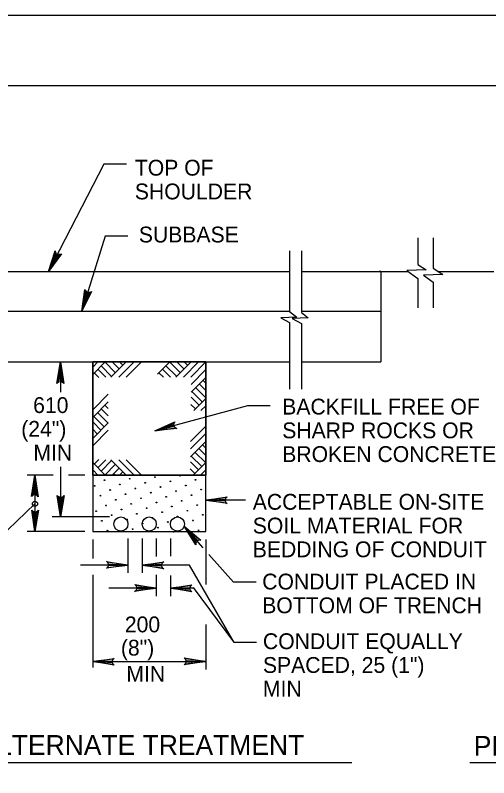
# Model space of a CAD drawing. Extents: x 638448 to 639352, y 297825 to 299013.
# Drawn here: x 638554 to 638654.5, y 298851.5 to 299013.3 of the extents above; entities that cross this region are included whole.
import ezdxf

# ---------------------------------------------------------------- set-up
doc = ezdxf.new("R2010")
doc.units = 0
for name, color, linetype in [('1', 7, 'Continuous'), ('2', 7, 'Continuous'), ('3', 7, 'Continuous'), ('PLT-BNDY', 7, 'Continuous')]:
    doc.layers.add(name, color=color, linetype=linetype)

msp = doc.modelspace()

# ---------------------------------------------------------------- linework, layer by layer
at = {"layer": '1'}
msp.add_lwpolyline([(639272.65, 298434.29), (639272.65, 298998.29), (638486.65, 298998.29), (638486.65, 298434.29), (639272.65, 298434.29), (639272.65, 298460.65), (639072.65, 298460.65), (639072.65, 298525.33), (639272.65, 298525.33), (639272.65, 298554.29), (639072.65, 298554.29), (639072.65, 298434.29), (639151.45, 298434.29), (639151.45, 298460.65), (639151.45, 298434.29), (639228.45, 298434.29), (639228.45, 298460.65), (639228.45, 298448.33), (639272.65, 298448.33)], dxfattribs=at)
at = {"layer": '2'}
for p, q in [((638639.45, 298966.09), (638639.45, 298960.41)), ((638642.76, 298966.09), (638642.76, 298959.6)), ((638612.25, 298963.29), (638612.25, 298950.46)), ((638614.79, 298963.29), (638614.79, 298950.24)), ((638552.44, 298958.93), (638612.25, 298958.93)), ((638614.79, 298958.93), (638637.42, 298958.93)), ((638631.64, 298958.93), (638631.26, 298958.93)), ((638631.64, 298958.93), (638631.64, 298939.73)), ((638643.81, 298958.93), (638655.64, 298958.93)), ((638639.45, 298957.41), (638639.45, 298951.24)), ((638642.76, 298956.63), (638642.76, 298951.24)), ((638552.44, 298950.53), (638612.25, 298950.53)), ((638614.79, 298950.53), (638631.64, 298950.53)), ((638612.25, 298948.07), (638612.25, 298933.98)), ((638614.79, 298947.88), (638614.79, 298933.98)), ((638552.44, 298939.73), (638612.25, 298939.73)), ((638563.63, 298939.73), (638563.63, 298933.31)), ((638570.44, 298937.08), (638573.09, 298939.73)), ((638571.56, 298939.73), (638570.44, 298938.61)), ((638572.24, 298938.88), (638574.47, 298936.65)), ((638573.02, 298939.73), (638575.3, 298937.45)), ((638574.33, 298936.5), (638577.58, 298939.75)), ((638574.58, 298939.73), (638576.06, 298938.24)), ((638575.98, 298936.5), (638579.17, 298939.69)), ((638576.15, 298939.73), (638576.86, 298939.02)), ((638577.53, 298936.5), (638580.73, 298939.69)), ((638584.18, 298937.1), (638586.83, 298939.75)), ((638585.98, 298938.91), (638588.21, 298936.68)), ((638586.76, 298939.75), (638589.04, 298937.47)), ((638588.07, 298936.52), (638591.32, 298939.77)), ((638588.31, 298939.75), (638589.8, 298938.27)), ((638589.71, 298936.52), (638592.91, 298939.72)), ((638589.89, 298939.75), (638590.59, 298939.05)), ((638591.27, 298936.52), (638594.46, 298939.72)), ((638614.79, 298939.73), (638631.64, 298939.73)), ((638631.64, 298939.73), (638631.64, 298939.73)), ((638570.77, 298937.41), (638571.74, 298936.44)), ((638571.55, 298938.19), (638573.25, 298936.5)), ((638584.51, 298937.44), (638585.48, 298936.47)), ((638585.29, 298938.22), (638586.98, 298936.52)), ((638591.32, 298934.97), (638594.44, 298938.09)), ((638591.32, 298933.33), (638594.44, 298936.44)), ((638594.44, 298935.25), (638593.85, 298935.85)), ((638594.44, 298932.13), (638592.27, 298934.29)), ((638594.44, 298933.68), (638593.07, 298935.05)), ((638570.51, 298929.67), (638573.7, 298932.87)), ((638593.02, 298930.54), (638591.32, 298932.24)), ((638593.71, 298931.23), (638591.48, 298933.46)), ((638570.51, 298928.03), (638573.76, 298931.28)), ((638592.24, 298929.77), (638591.27, 298930.73)), ((638591.9, 298929.43), (638594.44, 298931.97)), ((638573.74, 298926.72), (638571.46, 298929)), ((638573.74, 298928.27), (638572.25, 298929.76)), ((638573.74, 298929.85), (638573.03, 298930.55)), ((638594.44, 298930.44), (638593.43, 298929.43)), ((638572.89, 298925.94), (638570.66, 298928.17)), ((638570.44, 298923.49), (638573.74, 298926.79)), ((638572.2, 298925.25), (638570.51, 298926.94)), ((638591.21, 298922.82), (638594.41, 298926.02)), ((638573.74, 298925.26), (638570.44, 298921.96)), ((638571.42, 298924.47), (638570.46, 298925.44)), ((638591.21, 298921.26), (638594.41, 298924.46)), ((638591.21, 298919.62), (638594.46, 298922.87)), ((638594.44, 298919.86), (638592.95, 298921.35)), ((638594.44, 298921.44), (638593.73, 298922.15)), ((638593.59, 298917.53), (638591.36, 298919.76)), ((638594.44, 298918.31), (638592.16, 298920.59)), ((638570.44, 298918.38), (638573.09, 298915.73)), ((638570.77, 298918.04), (638571.74, 298919.01)), ((638571.55, 298917.27), (638573.25, 298918.96)), ((638572.24, 298916.57), (638574.47, 298918.8)), ((638573.02, 298915.73), (638575.3, 298918.01)), ((638574.33, 298918.96), (638577.58, 298915.71)), ((638575.98, 298918.96), (638579.17, 298915.76)), ((638577.53, 298918.96), (638580.73, 298915.76)), ((638592.9, 298916.84), (638591.21, 298918.53)), ((638591.79, 298915.73), (638594.44, 298918.38)), ((638563.63, 298917.49), (638563.63, 298906.84)), ((638571.56, 298915.73), (638570.44, 298916.85)), ((638574.58, 298915.73), (638576.06, 298917.21)), ((638576.15, 298915.73), (638576.86, 298916.44)), ((638592.12, 298916.06), (638591.16, 298917.03)), ((638594.44, 298916.85), (638593.32, 298915.73)), ((638562.08, 298915.73), (638556.51, 298915.73)), ((638558.19, 298915.73), (638558.19, 298903.73)), ((638568.76, 298915.73), (638565.32, 298915.73)), ((638574.01, 298906.84), (638561.86, 298906.84)), ((638568.76, 298903.73), (638556.51, 298903.73)), ((638568.76, 298903.73), (638556.51, 298903.73)), ((638570.44, 298902.05), (638570.44, 298898)), ((638577.94, 298902.27), (638577.94, 298894.95)), ((638580.94, 298902.27), (638580.94, 298894.95)), ((638583.94, 298902.27), (638583.94, 298898.46)), ((638586.94, 298902.27), (638586.94, 298898.53)), ((638594.44, 298902.05), (638594.44, 298892.54)), ((638577.94, 298896.63), (638567.86, 298896.63)), ((638591.02, 298896.63), (638580.94, 298896.63)), ((638570.44, 298894.55), (638570.44, 298874.89)), ((638583.94, 298894.59), (638583.94, 298890.05)), ((638586.94, 298894.44), (638586.94, 298890.05)), ((638583.94, 298891.73), (638573.86, 298891.73)), ((638591.9, 298891.73), (638586.94, 298891.73)), ((638594.44, 298883.99), (638594.44, 298874.47)), ((638570.44, 298876.15), (638594.44, 298876.15))]:
    msp.add_line(p, q, dxfattribs=at)
for points in [[(638577.61, 298981.7), (638572.81, 298981.7), (638561.04, 298958.93)], [(638577.87, 298966.44), (638573.07, 298966.44), (638568.14, 298950.53)], [(638563.53, 298962.55), (638563.17, 298962.55), (638561.04, 298958.93), (638563.53, 298962.55), (638563.8, 298962.66), (638561.04, 298958.93), (638562.78, 298962.75), (638562.57, 298963.03), (638561.04, 298958.93), (638562.5, 298963.33), (638562.57, 298963.03)], [(638639.45, 298960.41), (638641.24, 298959.26), (638637.16, 298959.12), (638639.45, 298957.41)], [(638642.76, 298959.6), (638644.77, 298958.31), (638640.69, 298958.17), (638642.76, 298956.63)], [(638569.95, 298954.53), (638569.6, 298954.47), (638568.14, 298950.53), (638569.95, 298954.53), (638570.2, 298954.69), (638568.14, 298950.53), (638569.18, 298954.59), (638568.93, 298954.83), (638568.14, 298950.53), (638568.8, 298955.12), (638568.93, 298954.83)], [(638612.25, 298950.46), (638613.78, 298949.2), (638610.38, 298949.07), (638612.25, 298948.07)], [(638614.79, 298950.24), (638616.23, 298949.07), (638612.83, 298948.93), (638614.79, 298947.88)], [(638563.05, 298935.37), (638563.36, 298935.53), (638563.63, 298939.73), (638563.05, 298935.37), (638562.86, 298935.15), (638563.63, 298939.73), (638563.8, 298935.53), (638564.12, 298935.38), (638563.63, 298939.73), (638564.32, 298935.14), (638564.12, 298935.38)], [(638570.44, 298939.73), (638594.44, 298939.73), (638594.44, 298915.73), (638570.44, 298915.73), (638570.44, 298939.73)], [(638570.44, 298915.73), (638570.44, 298939.73), (638594.44, 298939.73)], [(638570.44, 298915.73), (638594.44, 298915.73), (638594.44, 298939.73)], [(638570.44, 298939.73), (638570.44, 298915.73), (638594.44, 298915.73)], [(638594.44, 298939.73), (638594.44, 298915.73), (638570.44, 298915.73), (638570.44, 298938.32)], [(638570.44, 298938.9), (638570.44, 298939.73), (638594.44, 298939.73)], [(638570.44, 298939.73), (638570.44, 298915.73), (638594.44, 298915.73), (638594.44, 298939.73), (638570.44, 298939.73)], [(638608.12, 298930.4), (638603.32, 298930.4), (638583.66, 298925.14)], [(638588.01, 298925.74), (638587.77, 298926), (638583.66, 298925.14), (638588.01, 298925.74), (638588.28, 298925.61), (638583.66, 298925.14), (638587.66, 298926.42), (638587.73, 298926.77), (638583.66, 298925.14), (638587.9, 298927.03), (638587.73, 298926.77)], [(638557.61, 298911.37), (638557.93, 298911.53), (638558.19, 298915.73), (638557.61, 298911.37), (638557.42, 298911.15), (638558.19, 298915.73), (638558.37, 298911.53), (638558.68, 298911.38), (638558.19, 298915.73), (638558.88, 298911.14), (638558.68, 298911.38)], [(638564.21, 298911.19), (638563.89, 298911.03), (638563.63, 298906.84), (638564.21, 298911.19), (638564.4, 298911.41), (638563.63, 298906.84), (638563.45, 298911.03), (638563.14, 298911.19), (638563.63, 298906.84), (638562.93, 298911.42), (638563.14, 298911.19)], [(638544.2, 298898.57), (638546.6, 298898.57), (638558.19, 298909.62)], [(638598.8, 298909.86), (638598.64, 298910.18), (638594.44, 298910.41), (638598.8, 298909.86), (638599.02, 298909.67), (638594.44, 298910.41), (638598.63, 298910.62), (638598.79, 298910.93), (638594.44, 298910.41), (638599.02, 298911.14), (638598.79, 298910.93)], [(638602.86, 298910.41), (638598.06, 298910.41), (638594.44, 298910.41)], [(638558.77, 298908.08), (638558.45, 298907.92), (638558.19, 298903.73), (638558.77, 298908.08), (638558.96, 298908.3), (638558.19, 298903.73), (638558.01, 298907.92), (638557.7, 298908.08), (638558.19, 298903.73), (638557.5, 298908.31), (638557.7, 298908.08)], [(638592.34, 298901.23), (638592.47, 298901.56), (638589.86, 298904.86), (638592.34, 298901.23), (638592.34, 298900.94), (638589.86, 298904.86), (638592.79, 298901.86), (638593.13, 298901.95), (638589.86, 298904.86), (638593.44, 298901.91), (638593.13, 298901.95)], [(638593.92, 298900.26), (638589.86, 298904.86)], [(638605.14, 298892.99), (638600.34, 298892.99), (638595.13, 298898.9)], [(638573.59, 298897.21), (638573.75, 298896.9), (638577.94, 298896.63), (638573.59, 298897.21), (638573.36, 298897.4), (638577.94, 298896.63), (638573.75, 298896.46), (638573.59, 298896.14), (638577.94, 298896.63), (638573.35, 298895.94), (638573.59, 298896.14)], [(638585.29, 298896.05), (638585.13, 298896.37), (638580.94, 298896.63), (638585.29, 298896.05), (638585.52, 298895.86), (638580.94, 298896.63), (638585.13, 298896.81), (638585.29, 298897.12), (638580.94, 298896.63), (638585.53, 298897.33), (638585.29, 298897.12)], [(638605.26, 298880.23), (638600.46, 298880.23), (638591.02, 298896.63)], [(638579.59, 298892.31), (638579.75, 298891.99), (638583.94, 298891.73), (638579.59, 298892.31), (638579.36, 298892.5), (638583.94, 298891.73), (638579.75, 298891.55), (638579.59, 298891.24), (638583.94, 298891.73), (638579.35, 298891.03), (638579.59, 298891.24)], [(638591.29, 298891.15), (638591.13, 298891.46), (638586.94, 298891.73), (638591.29, 298891.15), (638591.52, 298890.96), (638586.94, 298891.73), (638591.13, 298891.9), (638591.29, 298892.22), (638586.94, 298891.73), (638591.53, 298892.42), (638591.29, 298892.22)], [(638591.78, 298891.85), (638600.34, 298880.35)], [(638574.79, 298875.57), (638574.63, 298875.89), (638570.44, 298876.15), (638574.79, 298875.57), (638575.02, 298875.38), (638570.44, 298876.15), (638574.63, 298876.33), (638574.79, 298876.64), (638570.44, 298876.15), (638575.03, 298876.84), (638574.79, 298876.64)], [(638590.09, 298876.73), (638590.25, 298876.41), (638594.44, 298876.15), (638590.09, 298876.73), (638589.86, 298876.92), (638594.44, 298876.15), (638590.25, 298875.97), (638590.09, 298875.66), (638594.44, 298876.15), (638589.85, 298875.46), (638590.09, 298875.66)]]:
    msp.add_lwpolyline(points, dxfattribs=at)
msp.add_lwpolyline([(638570.44, 298915.73), (638570.44, 298903.73), (638594.44, 298903.73), (638594.44, 298915.73)], close=True, dxfattribs=at)
for centre, radius in [((638572.94, 298914.63), 0.0798), ((638575.02, 298915.83), 0.0798), ((638578.3, 298914.95), 0.0798), ((638583.66, 298915.28), 0.0798), ((638586.94, 298914.4), 0.0798), ((638589.01, 298915.6), 0.0798), ((638592.29, 298914.72), 0.0798), ((638570.87, 298913.43), 0.0798), ((638576.22, 298913.75), 0.0798), ((638579.5, 298912.88), 0.0798), ((638581.58, 298914.08), 0.0798), ((638584.86, 298913.2), 0.0798), ((638590.21, 298913.52), 0.0798), ((638572.07, 298911.35), 0.0798), ((638574.14, 298912.55), 0.0798), ((638577.42, 298911.68), 0.0798), ((638582.78, 298912), 0.0798), ((638586.06, 298911.12), 0.0798), ((638588.14, 298912.32), 0.0798), ((638591.41, 298911.44), 0.0798), ((638593.49, 298912.64), 0.0798), ((638558.19, 298909.62), 0.547), ((638575.34, 298910.48), 0.0798), ((638578.62, 298909.6), 0.0798), ((638580.7, 298910.8), 0.0798), ((638583.98, 298909.92), 0.0798), ((638589.34, 298910.24), 0.0798), ((638571.19, 298908.08), 0.0798), ((638573.27, 298909.28), 0.0798), ((638576.54, 298908.4), 0.0798), ((638581.9, 298908.72), 0.0798), ((638587.26, 298909.04), 0.0798), ((638590.54, 298908.16), 0.0798), ((638592.61, 298909.36), 0.0798), ((638574.47, 298907.2), 0.0798), ((638576.44, 298905.34), 1.5), ((638577.74, 298906.32), 0.0798), ((638579.82, 298907.52), 0.0798), ((638582.44, 298905.34), 1.5), ((638582.44, 298905.34), 1.5), ((638583.1, 298906.64), 0.0798), ((638585.18, 298907.84), 0.0798), ((638588.44, 298905.34), 1.5), ((638588.46, 298906.96), 0.0798), ((638593.81, 298907.28), 0.0798), ((638572.39, 298906), 0.0798), ((638581.02, 298905.44), 0.0798), ((638586.38, 298905.76), 0.0798), ((638591.74, 298906.08), 0.0798), ((638573.59, 298903.92), 0.0798), ((638578.94, 298904.24), 0.0798), ((638584.3, 298904.56), 0.0798), ((638587.58, 298903.68), 0.0798), ((638592.94, 298904), 0.0798)]:
    msp.add_circle(centre, radius, dxfattribs=at)
at = {"layer": '3'}
for p, q in [((638545.02, 298854.72), (638625.44, 298854.72)), ((638650.55, 298854.72), (638730.67, 298854.72))]:
    msp.add_line(p, q, dxfattribs=at)
at = {"layer": 'PLT-BNDY'}
msp.add_lwpolyline([(638447.65, 299013.29), (639288.65, 299013.29), (639288.65, 298419.29), (638447.65, 298419.29)], close=True, dxfattribs=at)

# ---------------------------------------------------------------- texts
at = {"layer": '3'}
for s, height, p in [('TOP OF', 3.36, (638579.39, 298979.26)), ('SHOULDER', 3.36, (638579.39, 298974.22)), ('SUBBASE', 3.36, (638580.24, 298965.08)), ('610', 3.36, (638557.8, 298928.89)), ('BACKFILL FREE OF', 3.36, (638610.69, 298928.57)), ('(24")', 3.36, (638555.27, 298923.85)), ('SHARP ROCKS OR', 3.36, (638610.69, 298923.53)), ('MIN', 3.36, (638557.85, 298918.81)), ('BROKEN CONCRETE', 3.36, (638610.69, 298918.49)), ('ACCEPTABLE ON-SITE', 3.36, (638604.43, 298908.37)), ('SOIL MATERIAL FOR', 3.36, (638604.43, 298903.33)), ('BEDDING OF CONDUIT', 3.36, (638604.43, 298898.29)), ('CONDUIT PLACED IN', 3.36, (638606.44, 298891.45)), ('BOTTOM OF TRENCH', 3.36, (638606.44, 298886.41)), ('200', 3.36, (638577.27, 298882.36)), ('CONDUIT EQUALLY', 3.36, (638606.59, 298878.79)), ('(8")', 3.36, (638576.43, 298877.42)), ('SPACED, 25 (1")', 3.36, (638606.59, 298873.75)), ('MIN', 3.36, (638577.59, 298871.86)), ('MIN', 3.36, (638606.59, 298868.71)), ('ALTERNATE TREATMENT', 4.2, (638546.4, 298856.35)), ('PREFERRED TREATMENT', 4.2, (638651.36, 298856.17))]:
    msp.add_text(s, height=height, dxfattribs=at).set_placement(p)

doc.saveas('drawing.dxf')
